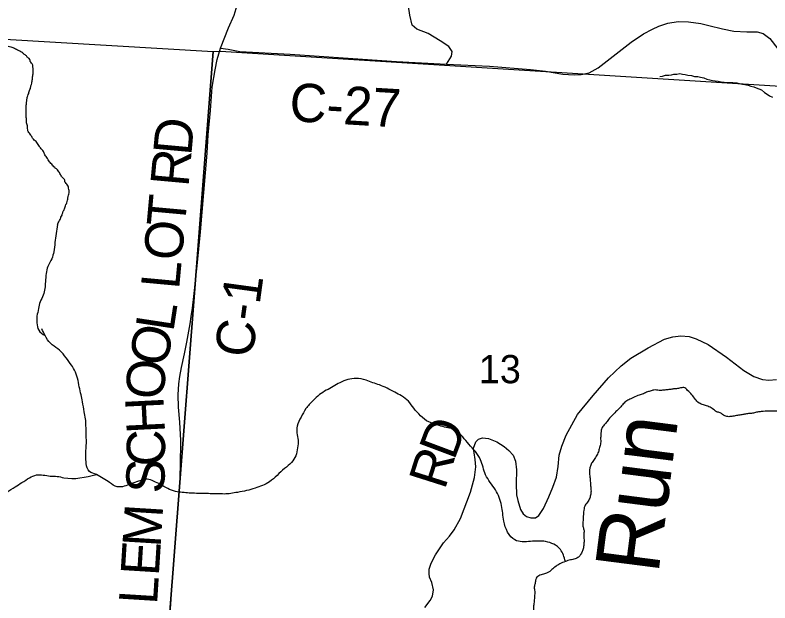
# Model space of a CAD drawing. Extents: x -13.7 to 34, y 0 to 32.3.
# Drawn here: x 28.447 to 29.565, y 15.038 to 15.91 of the extents above; entities that cross this region are included whole.
import ezdxf

# ---------------------------------------------------------------- set-up
doc = ezdxf.new("R2010")
doc.units = 0
for name, color, linetype in [('GM_X_Corporation', 7, 'Continuous'), ('GM_X_County_Road', 7, 'Continuous'), ('GM_X_County_Road_Text', 7, 'Continuous'), ('GM_X_Minor_River', 7, 'Continuous'), ('GM_X_Minor_River_Text', 7, 'Continuous'), ('GM_X_Section_Text', 7, 'Continuous'), ('GM_X_Township_Road', 7, 'Continuous'), ('GM_X_Township_Road_Text', 7, 'Continuous')]:
    doc.layers.add(name, color=color, linetype=linetype)

msp = doc.modelspace()

# ---------------------------------------------------------------- linework, layer by layer
at = {"layer": 'GM_X_Corporation'}
for points in [[(27.73, 15.9158), (28.7402, 15.8562), (28.6615, 14.8398), (27.6593, 14.9006)], [(28.7402, 15.8562), (28.7512, 15.8567), (29.7549, 15.7939), (29.6625, 14.7774), (28.6615, 14.8398)]]:
    msp.add_lwpolyline(points, close=True, dxfattribs=at)
at = {"layer": 'GM_X_County_Road'}
for points in [[(28.751, 15.861), (28.763, 15.8911), (28.7712, 15.91), (28.7786, 15.9349), (28.7869, 15.9798)], [(28.751, 15.861), (28.7623, 15.8593), (28.7796, 15.8562), (28.8544, 15.8522), (29.012, 15.8413), (29.0862, 15.8371), (29.1499, 15.8343), (29.2104, 15.8294), (29.2328, 15.8268), (29.2585, 15.8226), (29.2751, 15.8212), (29.2856, 15.8221), (29.2975, 15.8245), (29.3106, 15.8317), (29.3594, 15.8698), (29.3778, 15.8824), (29.3913, 15.8889), (29.4004, 15.8936), (29.4142, 15.898), (29.4294, 15.9006), (29.4446, 15.8999), (29.4628, 15.8976), (29.4747, 15.8947), (29.4952, 15.8896), (29.5118, 15.8859), (29.5312, 15.8854), (29.5464, 15.8854), (29.5555, 15.8828), (29.565, 15.8754), (29.5769, 15.86)], [(28.6766, 15.0223), (28.6792, 15.0656), (28.6813, 15.0938), (28.6874, 15.1704), (28.6906, 15.2131), (28.6916, 15.2418), (28.6921, 15.2791), (28.6908, 15.3066), (28.6889, 15.3287), (28.6885, 15.3467), (28.6895, 15.3634), (28.6906, 15.3739), (28.6933, 15.3874), (28.6977, 15.4075), (28.7013, 15.425), (28.7062, 15.452), (28.7075, 15.4632), (28.7096, 15.4756), (28.7113, 15.4925), (28.7167, 15.5383), (28.7214, 15.5886), (28.7313, 15.7051), (28.733, 15.7323), (28.7362, 15.7684), (28.7387, 15.803), (28.7431, 15.829), (28.7463, 15.8442), (28.751, 15.861)]]:
    msp.add_lwpolyline(points, dxfattribs=at)
at = {"layer": 'GM_X_Minor_River'}
msp.add_lwpolyline([(29.4022, 15.8189), (29.4063, 15.8193), (29.4105, 15.8208), (29.4155, 15.8208), (29.4192, 15.8216), (29.423, 15.8224), (29.4272, 15.8224), (29.4318, 15.8232), (29.4356, 15.8224), (29.4398, 15.8217), (29.4436, 15.8209), (29.4489, 15.8202), (29.4534, 15.819), (29.4584, 15.8187), (29.4625, 15.8179), (29.4671, 15.8168), (29.472, 15.8149), (29.4762, 15.8142), (29.48, 15.813), (29.4842, 15.8127), (29.4884, 15.8119), (29.4929, 15.8108), (29.4975, 15.8104), (29.5021, 15.8101), (29.5062, 15.8101), (29.5104, 15.8101), (29.5161, 15.8093), (29.5199, 15.8086), (29.5245, 15.8078), (29.5283, 15.8071), (29.5332, 15.806), (29.537, 15.8048), (29.5412, 15.8037), (29.545, 15.8022), (29.5488, 15.8007), (29.5526, 15.7992), (29.5572, 15.7954), (29.561, 15.7927), (29.5648, 15.7901), (29.5693, 15.7882)], dxfattribs=at)
for points in [[(28.5097, 15.5993), (28.5105, 15.6019), (28.5125, 15.6053), (28.5141, 15.6083), (28.5146, 15.6105), (28.5162, 15.6135), (28.5175, 15.618), (28.5199, 15.6229), (28.5208, 15.6255), (28.522, 15.6289), (28.5233, 15.6315), (28.5242, 15.6357), (28.525, 15.6387), (28.5259, 15.6432), (28.5268, 15.6462), (28.5269, 15.6489), (28.5262, 15.6512), (28.5256, 15.655), (28.5223, 15.6604), (28.5205, 15.6628), (28.5202, 15.6651), (28.5169, 15.669), (28.514, 15.6736), (28.5104, 15.6791), (28.5086, 15.6814), (28.5053, 15.6838), (28.5009, 15.6889), (28.4987, 15.6912), (28.4965, 15.694), (28.4929, 15.7002), (28.4907, 15.7029), (28.4886, 15.7079), (28.4853, 15.7118), (28.482, 15.7165), (28.4777, 15.7223), (28.4751, 15.7247), (28.4725, 15.7274), (28.47, 15.7321), (28.4678, 15.7348), (28.466, 15.7372), (28.4654, 15.7398), (28.4645, 15.7475), (28.4638, 15.7502), (28.4635, 15.7528), (28.4633, 15.7582), (28.463, 15.7608), (28.4632, 15.7654), (28.463, 15.7726), (28.4631, 15.7764), (28.4636, 15.7798), (28.4642, 15.7851), (28.4647, 15.7877), (28.4655, 15.7904), (28.4668, 15.7938), (28.4676, 15.7968), (28.4697, 15.8024), (28.4702, 15.805), (28.471, 15.8073), (28.4715, 15.8107), (28.472, 15.8133), (28.4724, 15.8164), (28.4729, 15.8201), (28.4735, 15.8254), (28.4736, 15.8285), (28.473, 15.8338), (28.472, 15.8377), (28.4698, 15.84), (28.4677, 15.8454), (28.4655, 15.847), (28.4626, 15.8501), (28.4603, 15.8517), (28.4574, 15.8545), (28.4551, 15.8557), (28.4488, 15.8589), (28.4458, 15.8602), (28.4436, 15.8614), (28.4406, 15.8626), (28.4364, 15.8632), (28.4323, 15.8644), (28.4289, 15.8649), (28.4262, 15.865), (28.4228, 15.8659), (28.4191, 15.8672), (28.4161, 15.8676), (28.4115, 15.8689), (28.409, 15.8713), (28.4072, 15.8744), (28.405, 15.8779), (28.4025, 15.8818), (28.4014, 15.8848), (28.4017, 15.892), (28.4021, 15.8947), (28.4019, 15.8974), (28.4016, 15.8997), (28.399, 15.9024), (28.3968, 15.9036), (28.3923, 15.9068)], [(28.5097, 15.5993), (28.5057, 15.5727), (28.5041, 15.559), (28.5009, 15.5487), (28.4952, 15.5374), (28.4928, 15.5267), (28.4916, 15.5146), (28.4908, 15.5047), (28.4885, 15.4945), (28.4838, 15.4846), (28.4815, 15.4747), (28.4791, 15.4637), (28.4791, 15.4535), (28.4817, 15.4428), (28.4911, 15.4348)], [(29.652, 15.5773), (29.6485, 15.5716), (29.6447, 15.5652), (29.6389, 15.5603), (29.6313, 15.5539), (29.626, 15.5517), (29.6206, 15.5465), (29.6156, 15.5408), (29.6125, 15.5348), (29.6098, 15.5276), (29.6082, 15.5219), (29.6077, 15.5151), (29.6088, 15.5082), (29.611, 15.5029), (29.6171, 15.4975), (29.6242, 15.4936), (29.6299, 15.4906), (29.6351, 15.4867), (29.6416, 15.4836), (29.648, 15.4786), (29.654, 15.4728), (29.6565, 15.4637), (29.6584, 15.4565), (29.6587, 15.4508), (29.6594, 15.442), (29.6597, 15.436), (29.66, 15.4303), (29.6618, 15.4219), (29.6636, 15.4166), (29.6659, 15.4112), (29.6673, 15.4055), (29.6688, 15.3983), (29.6717, 15.3869), (29.6724, 15.3808), (29.6716, 15.3755), (29.667, 15.3698), (29.6612, 15.3669), (29.6544, 15.3665), (29.6483, 15.3666), (29.6427, 15.3686), (29.6374, 15.3682), (29.6297, 15.3653), (29.6229, 15.3612), (29.6175, 15.3582), (29.6122, 15.3548), (29.6106, 15.3491), (29.6086, 15.3431), (29.6059, 15.337), (29.6036, 15.3314), (29.5975, 15.3273), (29.5921, 15.3254), (29.5864, 15.3236), (29.5811, 15.3229), (29.575, 15.3229), (29.569, 15.3226), (29.5637, 15.3227), (29.5523, 15.322), (29.547, 15.3213), (29.5409, 15.3198), (29.5348, 15.3192), (29.5291, 15.3184), (29.5238, 15.3174), (29.5173, 15.3163), (29.5105, 15.3152), (29.5044, 15.3145), (29.4983, 15.3157), (29.4916, 15.32), (29.4863, 15.3219), (29.4799, 15.3265), (29.4731, 15.33), (29.4666, 15.332), (29.4602, 15.3347), (29.4546, 15.3405), (29.4497, 15.347), (29.4433, 15.3535), (29.4377, 15.3577), (29.4312, 15.3566), (29.4252, 15.3559), (29.4198, 15.3552), (29.4141, 15.3545), (29.4077, 15.3538), (29.4012, 15.3535), (29.3933, 15.354), (29.3879, 15.3525), (29.3826, 15.3507), (29.3761, 15.3477), (29.3697, 15.3459), (29.3609, 15.3418), (29.3548, 15.3388), (29.3491, 15.3347), (29.3441, 15.329), (29.3383, 15.3234), (29.3326, 15.3174), (29.326, 15.3102), (29.3222, 15.305), (29.3176, 15.2997), (29.3153, 15.2944)], [(29.1009, 15.2954), (29.0805, 15.2997), (29.0695, 15.3032), (29.0597, 15.3067), (29.0476, 15.3159), (29.0374, 15.327), (29.0295, 15.3373), (29.0193, 15.3453), (29.0095, 15.3507), (28.9978, 15.3568), (28.9868, 15.3615), (28.9766, 15.3649), (28.9667, 15.3684), (28.952, 15.3712), (28.9398, 15.3694), (28.928, 15.3649), (28.9181, 15.3592), (28.9078, 15.3536), (28.8979, 15.3472), (28.888, 15.3381), (28.8777, 15.3264), (28.8704, 15.3139), (28.8646, 15.3006), (28.8642, 15.2904), (28.866, 15.2797), (28.8652, 15.2683), (28.8625, 15.2565), (28.8563, 15.2467), (28.846, 15.2376), (28.8349, 15.2274), (28.8239, 15.218), (28.8132, 15.2124), (28.8022, 15.2086), (28.7897, 15.2049), (28.7764, 15.2023), (28.7665, 15.2005), (28.7566, 15.1998), (28.7456, 15.2002), (28.7358, 15.2003), (28.7259, 15.2007), (28.7153, 15.2008), (28.7047, 15.2012), (28.6944, 15.2021), (28.6846, 15.2036), (28.6728, 15.2079), (28.6619, 15.214), (28.652, 15.2187), (28.6422, 15.2218), (28.6297, 15.2188), (28.6183, 15.2147), (28.6084, 15.2113), (28.5977, 15.2106), (28.5868, 15.2168), (28.577, 15.2229), (28.5671, 15.2287), (28.5569, 15.2333), (28.5521, 15.2451), (28.5514, 15.2558), (28.5518, 15.2672), (28.5523, 15.2774), (28.552, 15.2888), (28.5517, 15.301), (28.551, 15.3113), (28.5492, 15.3219), (28.5466, 15.3367), (28.5444, 15.347), (28.5418, 15.3588), (28.5392, 15.3714), (28.5348, 15.3836), (28.5284, 15.3935), (28.5201, 15.4046), (28.5099, 15.4153), (28.499, 15.4233), (28.4911, 15.4348), (28.4862, 15.4447)], [(29.2621, 15.0998), (29.2547, 15.1177), (29.2328, 15.1293), (29.2104, 15.1295), (29.1873, 15.1317), (29.1709, 15.1596), (29.1677, 15.1827), (29.1584, 15.206), (29.1439, 15.2285), (29.1365, 15.2506), (29.1193, 15.2736), (29.1009, 15.2954)], [(29.3153, 15.2944), (29.3148, 15.2891), (29.3144, 15.283), (29.3143, 15.2754), (29.3127, 15.2686), (29.3111, 15.2625), (29.3077, 15.2557), (29.3038, 15.2493), (29.3003, 15.2441), (29.2984, 15.2384), (29.2983, 15.2262), (29.299, 15.2205), (29.2993, 15.2133), (29.3, 15.2076), (29.2999, 15.2008), (29.2987, 15.1951), (29.296, 15.1894), (29.2917, 15.1834), (29.2894, 15.1758), (29.2885, 15.1637), (29.2881, 15.1569), (29.2884, 15.1508), (29.2898, 15.1455), (29.2894, 15.139), (29.2897, 15.1337), (29.2897, 15.1272), (29.2888, 15.12), (29.2869, 15.1144), (29.2818, 15.1064), (29.2765, 15.1038), (29.2697, 15.102), (29.2621, 15.0998), (29.2541, 15.0961), (29.2483, 15.0927), (29.2422, 15.0878), (29.2353, 15.083), (29.2296, 15.0811), (29.2228, 15.0786), (29.2182, 15.0733), (29.2173, 15.0672), (29.2161, 15.0619), (29.2168, 15.0555), (29.2164, 15.0482), (29.2159, 15.0414), (29.2151, 15.0338), (29.2146, 15.0255), (29.2134, 15.0183), (29.2126, 15.0126), (29.2114, 15.0065), (29.211, 15.0012), (29.2098, 14.9959), (29.2078, 14.9895), (29.2062, 14.9823), (29.2043, 14.9766), (29.2031, 14.9694), (29.2022, 14.9626), (29.2014, 14.9573), (29.201, 14.952), (29.2001, 14.9406), (29.2, 14.9345), (29.2004, 14.9281), (29.203, 14.9227), (29.2067, 14.9162), (29.2131, 14.909), (29.2172, 14.9028), (29.2243, 14.8948), (29.2292, 14.8887), (29.2348, 14.8856), (29.2405, 14.8806), (29.2487, 14.874), (29.2544, 14.8706), (29.2597, 14.8652), (29.2687, 14.8583), (29.274, 14.8552), (29.28, 14.8494), (29.2852, 14.8445), (29.2931, 14.8372), (29.2999, 14.8318), (29.3052, 14.8283), (29.3105, 14.8256), (29.3176, 14.8221), (29.3244, 14.8179), (29.3305, 14.814), (29.3369, 14.8113), (29.3425, 14.8086), (29.3478, 14.8055), (29.3535, 14.8028), (29.3606, 14.797), (29.3663, 14.7924), (29.3715, 14.7885), (29.3776, 14.7862), (29.3844, 14.7816), (29.3911, 14.7758), (29.3972, 14.7742), (29.4033, 14.773), (29.4093, 14.773), (29.415, 14.7733)], [(27.5226, 15.1494), (27.5325, 15.144), (27.5426, 15.1352), (27.5528, 15.1283), (27.5649, 15.1222), (27.574, 15.11), (27.5765, 15.0967), (27.5795, 15.086), (27.5855, 15.0742), (27.5957, 15.0616), (27.6062, 15.0528), (27.6149, 15.0424), (27.6228, 15.0321), (27.6333, 15.0199), (27.6431, 15.0107), (27.6541, 15.0012), (27.6639, 14.9924), (27.674, 14.9828), (27.6842, 14.9721), (27.6951, 14.9614), (27.7064, 14.9484), (27.7159, 14.9381), (27.7256, 14.9262), (27.7354, 14.9163), (27.7445, 14.906), (27.7543, 14.8964), (27.7667, 14.8865), (27.7765, 14.878), (27.789, 14.87), (27.8007, 14.8619), (27.8105, 14.8562), (27.8223, 14.85), (27.8362, 14.8431), (27.8461, 14.8392), (27.8567, 14.8357), (27.8817, 14.8295), (27.8927, 14.8287), (27.9033, 14.8305), (27.914, 14.8373), (27.9239, 14.8456), (27.9365, 14.8569), (27.9483, 14.8705), (27.9575, 14.8804), (27.9671, 14.8913), (27.9774, 14.9038), (27.9896, 14.9117), (28.0037, 14.9185), (28.0166, 14.923), (28.0303, 14.9267), (28.0432, 14.9308), (28.0554, 14.9353), (28.0706, 14.9413), (28.0808, 14.9465), (28.0915, 14.9506), (28.1048, 14.9566), (28.1155, 14.9611), (28.1303, 14.9687), (28.141, 14.9728), (28.1528, 14.9799), (28.1627, 14.9863), (28.1733, 14.9923), (28.1863, 14.9995), (28.1977, 15.0063), (28.2076, 15.0111), (28.2175, 15.0156), (28.2319, 15.0205), (28.243, 15.0277), (28.2563, 15.0401), (28.2663, 15.0503), (28.2755, 15.0624), (28.2839, 15.0764), (28.2897, 15.0878), (28.295, 15.098), (28.3004, 15.1109), (28.3047, 15.1238), (28.3089, 15.1352), (28.3136, 15.1454), (28.3189, 15.1576), (28.3247, 15.1674), (28.3457, 15.1882), (28.3564, 15.1942), (28.3666, 15.1953), (28.3768, 15.1914), (28.3886, 15.1906), (28.4003, 15.1913), (28.4117, 15.1931), (28.4228, 15.1972), (28.4342, 15.2025), (28.4468, 15.2104), (28.4567, 15.2168), (28.4681, 15.2239), (28.4784, 15.2281), (28.4882, 15.228), (28.4988, 15.2264), (28.5091, 15.226), (28.5189, 15.224), (28.5671, 15.2287)]]:
    msp.add_spline(points, degree=3, dxfattribs=at)
at = {"layer": 'GM_X_Township_Road'}
for points in [[(29.0862, 15.8371), (29.0934, 15.849), (29.0944, 15.8562), (29.0895, 15.8635), (29.0766, 15.8716), (29.0589, 15.8828), (29.0421, 15.8889), (29.0351, 15.8949), (29.0318, 15.9099), (29.0299, 15.9232), (29.0404, 15.9309), (29.0556, 15.9396), (29.0706, 15.947), (29.0701, 15.9562), (29.0766, 15.9615), (29.0953, 15.9702), (29.138, 16.004)], [(29.054, 15.0314), (29.0617, 15.0417), (29.0651, 15.0485), (29.0666, 15.0576), (29.064, 15.0688), (29.061, 15.0765), (29.0601, 15.0818), (29.0603, 15.0884), (29.0631, 15.0973), (29.0699, 15.1096), (29.0815, 15.1274), (29.0904, 15.1374), (29.0972, 15.1465), (29.1065, 15.1636), (29.1217, 15.2025), (29.1273, 15.2243), (29.1296, 15.2401), (29.1285, 15.2511), (29.1268, 15.2611), (29.1261, 15.2677), (29.1294, 15.277), (29.1334, 15.2812), (29.1394, 15.2831), (29.1483, 15.2819), (29.1607, 15.277), (29.1714, 15.2702), (29.1782, 15.2644), (29.1847, 15.2572), (29.188, 15.2485), (29.1896, 15.2359), (29.1894, 15.2147), (29.1899, 15.1986), (29.1915, 15.1902), (29.1957, 15.1771), (29.1997, 15.1706), (29.2046, 15.1666), (29.2109, 15.1645), (29.2179, 15.1643), (29.2228, 15.1678), (29.2298, 15.1783), (29.2375, 15.1958), (29.2436, 15.2098), (29.2492, 15.2247), (29.2513, 15.2406), (29.2529, 15.2574), (29.2571, 15.2707), (29.2632, 15.2871), (29.28, 15.3179), (29.3031, 15.3459), (29.3262, 15.372), (29.3446, 15.39), (29.3589, 15.4012), (29.3846, 15.4164), (29.4091, 15.4295), (29.4215, 15.433), (29.4334, 15.4346), (29.4457, 15.4333), (29.4562, 15.4297), (29.4737, 15.4213), (29.5008, 15.4028), (29.5267, 15.3832), (29.5412, 15.3739), (29.5541, 15.3695), (29.5636, 15.3685), (29.5748, 15.3695)]]:
    msp.add_lwpolyline(points, dxfattribs=at)

# ---------------------------------------------------------------- texts
at = {"layer": 'GM_X_County_Road_Text'}
for s, height, rotation, p in [('C-27', 0.05682, 356.5725, (28.8521, 15.753)), ('D', 0.0568, 84.7947, (28.7077, 15.7006)), ('R', 0.0568, 84.797, (28.7035, 15.6542)), ('T', 0.0568, 84.7943, (28.6981, 15.5944)), ('O', 0.0568, 84.7966, (28.6935, 15.5446)), ('L', 0.0568, 84.7508, (28.6896, 15.5022)), ('C-1', 0.05682, 82.2609, (28.7982, 15.4003)), ('L', 0.0568, 81.3146, (28.6811, 15.4391)), ('O', 0.0568, 78.0449, (28.6702, 15.3867)), ('O', 0.0568, 85.4418, (28.6665, 15.3388)), ('H', 0.0568, 92.911, (28.669, 15.2908)), ('C', 0.0568, 89.6823, (28.6688, 15.2406)), ('S', 0.0568, 87.5722, (28.6672, 15.2001)), ('M', 0.0568, 86.455, (28.6623, 15.1198)), ('E', 0.0568, 86.4277, (28.6596, 15.0774)), ('L', 0.0568, 86.4303, (28.657, 15.035))]:
    msp.add_text(s, height=height, rotation=rotation, dxfattribs=at).set_placement(p)
at = {"layer": 'GM_X_Minor_River_Text'}
msp.add_text('Run', height=0.09471, rotation=82.6901, dxfattribs=at).set_placement((29.3998, 15.0798))
at = {"layer": 'GM_X_Section_Text'}
msp.add_text('13', height=0.04186, rotation=0, dxfattribs=at).set_placement((29.1339, 15.3641))
at = {"layer": 'GM_X_Township_Road_Text'}
for s, rotation, p in [('D', 69.4542, (29.0972, 15.2485)), ('R', 72.371, (29.0833, 15.2048))]:
    msp.add_text(s, height=0.0568, rotation=rotation, dxfattribs=at).set_placement(p)

doc.saveas('drawing.dxf')
